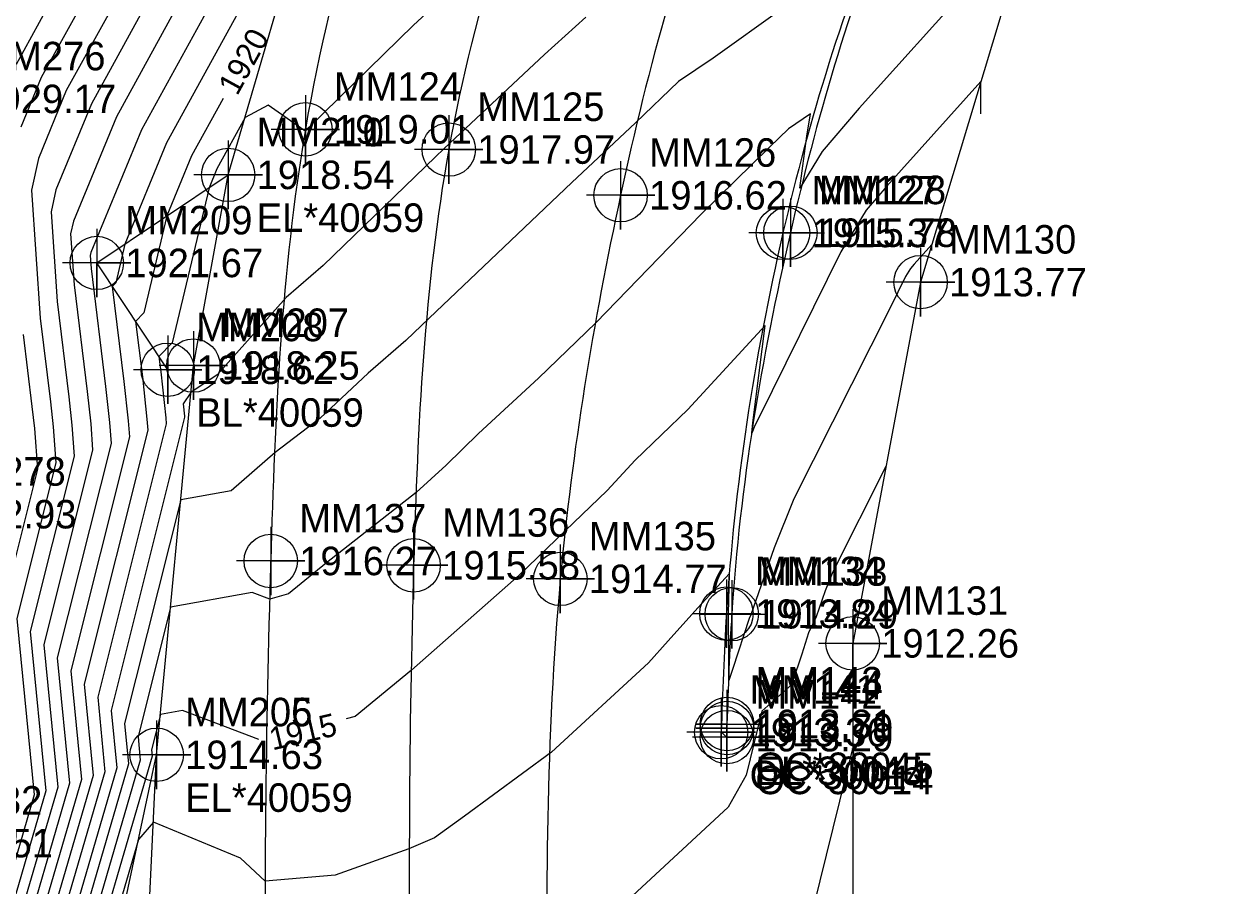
# Model space of a CAD drawing. Extents: x 1004378 to 1005103, y 553854 to 554288.
# Drawn here: x 1004979.8 to 1005086, y 554119.4 to 554194.9 of the extents above; entities that cross this region are included whole.
import ezdxf

# ---------------------------------------------------------------- set-up
doc = ezdxf.new("R2010")
doc.units = 0
for name, color, linetype in [('DTM Contours Major', 7, 'Continuous'), ('DTM Contours Major Text', 7, 'Continuous'), ('DTM Contours Minor', 7, 'Continuous'), ('Exist DTM Breakline', 7, 'Continuous'), ('Exist DTM Breakline Cogo Comment', 7, 'Continuous'), ('Exist DTM Breakline Cogo Elevation', 7, 'Continuous'), ('Exist DTM Breakline Cogo Number', 7, 'Continuous'), ('Exist DTM Breakline Cogo Point CELL', 7, 'Continuous'), ('Exist DTM Crownline', 7, 'Continuous'), ('Exist DTM Crownline Cogo Elevation', 7, 'Continuous'), ('Exist DTM Crownline Cogo Number', 7, 'Continuous'), ('Exist DTM Crownline Cogo Point CELL', 7, 'Continuous'), ('Exist Roads Curbs', 7, 'Continuous'), ('Exist Roads Curbs Cogo Comment', 7, 'Continuous'), ('Exist Roads Curbs Cogo Elevation', 7, 'Continuous'), ('Exist Roads Curbs Cogo Number', 7, 'Continuous'), ('Exist Roads Curbs Cogo Point CELL', 7, 'Continuous'), ('Exist Roads EOP', 7, 'Continuous'), ('Exist Roads EOP Cogo Comment', 7, 'Continuous'), ('Exist Roads EOP Cogo Elevation', 7, 'Continuous'), ('Exist Roads EOP Cogo Number', 7, 'Continuous'), ('Exist Roads EOP Cogo Point CELL', 7, 'Continuous')]:
    doc.layers.add(name, color=color, linetype=linetype)

msp = doc.modelspace()

# ---------------------------------------------------------------- linework, layer by layer
at = {"layer": 'DTM Contours Major'}
for points in [[(1004988.06, 554197.35), (1004983.52, 554189.09), (1004981.07, 554183.15), (1004980.47, 554180.38), (1004981.23, 554169.16), (1004982.13, 554161.83), (1004982.37, 554159.62), (1004982.6, 554156.48), (1004979.18, 554142.83), (1004980.71, 554127.37), (1004976.99, 554114.65), (1004972.24, 554102.28), (1004972.02, 554101.1)], [(1005063.7, 554187.05), (1005063.69, 554189.9), (1005055.44, 554180.71), (1005053.65, 554178.62), (1005051.42, 554174.96), (1005044.19, 554160.35), (1005043.88, 554159.74), (1005043.62, 554159.08), (1005043.7, 554159.98), (1005044.8, 554168.51), (1005038, 554161.15), (1005033.4, 554156.7), (1005030.95, 554154.05), (1005027.24, 554150.5), (1005023.22, 554146.64), (1005013.79, 554138.29), (1005008.85, 554134.25), (1005008.05, 554134.02)], [(1004997.26, 554188.39), (1004994.51, 554183.37), (1004992.34, 554178.11), (1004990.33, 554169.61), (1004989.59, 554168.86), (1004990.19, 554164.02), (1004990.59, 554160.29), (1004990.67, 554159.32), (1004985.09, 554137.07), (1004985.88, 554129.06), (1004980.68, 554111.25), (1004977.83, 554103.85), (1004975.65, 554092.33)], [(1005000.39, 554132.23), (1004993.71, 554134.75), (1004991.77, 554134.4), (1004990.99, 554131.31), (1004991.05, 554130.76), (1004984.36, 554107.86), (1004983.43, 554105.42), (1004981.8, 554096.83), (1004980.53, 554086.9), (1004982.36, 554084.87), (1004986.04, 554077.59), (1004986.97, 554072.11), (1004986.7, 554069.84), (1004986.54, 554062.8), (1004985.08, 554049.56), (1004984.33, 554046.83)]]:
    msp.add_lwpolyline(points, dxfattribs=at)
at = {"layer": 'DTM Contours Minor'}
for points in [[(1004977.31, 554222.08), (1004985.01, 554221.76), (1004987.05, 554222.46), (1004987.51, 554221.89), (1004987.45, 554221.55), (1004987.43, 554221.07), (1004987.36, 554220.82), (1004987.22, 554220.64), (1004985.6, 554198.02), (1004981.32, 554190.23), (1004979.53, 554185.89)], [(1004978.6, 554214.44), (1004982.9, 554211.38), (1004981.82, 554196.28), (1004979.12, 554191.37)], [(1005004.49, 554206.7), (1004992.31, 554184.52), (1004988.65, 554175.64), (1004987.85, 554172.24), (1004987.55, 554171.94), (1004988.57, 554163.59), (1004988.95, 554160.16), (1004989.05, 554158.75), (1004983.91, 554138.23), (1004984.84, 554128.73), (1004979.94, 554111.93)], [(1005000.71, 554204.97), (1004990.11, 554185.66), (1004985.68, 554174.91), (1004985.62, 554174.63), (1004985.7, 554173.51), (1004986.96, 554163.15), (1004987.3, 554160.02), (1004987.44, 554158.18), (1004982.73, 554139.38), (1004983.81, 554128.39), (1004979.2, 554112.61)], [(1004996.93, 554203.23), (1004987.92, 554186.8), (1004984.14, 554177.65), (1004983.9, 554176.55), (1004984.21, 554172.06), (1004985.35, 554162.71), (1004985.66, 554159.89), (1004985.83, 554157.61), (1004981.54, 554140.53), (1004982.77, 554128.05), (1004978.46, 554113.29)], [(1004993.15, 554201.49), (1004985.72, 554187.94), (1004982.61, 554180.4), (1004982.19, 554178.46), (1004982.72, 554170.61), (1004983.74, 554162.27), (1004984.01, 554159.76), (1004984.22, 554157.05), (1004980.36, 554141.68), (1004981.74, 554127.71), (1004977.73, 554113.97)], [(1005020.69, 554201.04), (1005013.96, 554194.83), (1005004.77, 554185.85), (1005004.59, 554185.68), (1005004.46, 554185.55), (1005004.34, 554185.62), (1005001.22, 554187.83), (1004999.19, 554186.75), (1004996.71, 554182.23), (1004996.03, 554180.58), (1004992.81, 554166.98), (1004991.64, 554165.79), (1004991.8, 554164.46), (1004992.24, 554160.42), (1004992.28, 554159.89), (1004986.27, 554135.92), (1004986.91, 554129.4), (1004981.41, 554110.58)], [(1005062.93, 554198.57), (1005053.02, 554187.55), (1005049.79, 554183.75), (1005047.84, 554180.55), (1005048.44, 554185.1), (1005048.77, 554187.05), (1005046.84, 554185.74), (1005045.17, 554184.14), (1005039.19, 554178.28), (1005029.95, 554168.74), (1005024.91, 554163.9), (1005019.67, 554159.04), (1005016.83, 554156.27), (1005014.19, 554153.86), (1005006.34, 554147.72), (1005003.01, 554144.99), (1005001.36, 554144.51), (1004999.81, 554145.1), (1004992.66, 554143.81), (1004989.81, 554132.46), (1004990.01, 554130.42), (1004983.63, 554108.54)], [(1005029.07, 554195.54), (1005025.44, 554192.27), (1005017.15, 554184.49), (1005016.63, 554183.99), (1005015.9, 554183.29), (1005006.03, 554173.76), (1005002.8, 554170.95), (1004996.74, 554164.18), (1004994.44, 554162.64), (1004993.77, 554161.63), (1004993.89, 554160.55), (1004993.89, 554160.46), (1004987.45, 554134.77), (1004987.95, 554129.74), (1004982.15, 554109.9)], [(1005046.28, 554196.26), (1005040.24, 554191.95), (1005037.2, 554189.88), (1005033.43, 554186.28), (1005027.84, 554181.05), (1005015.32, 554169.16), (1005013.29, 554167.2), (1005009.99, 554164.33), (1005005.79, 554160.4), (1005001.84, 554157.38), (1004997.96, 554154.02), (1004993.55, 554153.23), (1004988.63, 554133.62), (1004988.98, 554130.08), (1004982.89, 554109.22)], [(1005059.4, 554175.07), (1005059.4, 554175.6), (1005057.85, 554173.88), (1005057.52, 554173.49), (1005057.1, 554172.8), (1005055.74, 554170.07), (1005047.29, 554153.33), (1005045.59, 554149.03), (1005043.53, 554143.15), (1005043.38, 554142.84), (1005041.95, 554138.45), (1005041.61, 554137.4), (1005041.6, 554138.35), (1005041.59, 554139.54), (1005041.56, 554143.23), (1005041.66, 554146.77), (1005038.88, 554143.77), (1005036.28, 554140.86), (1005034.56, 554138.93), (1005026.07, 554131.11), (1005018.42, 554125.49), (1005015.8, 554123.59), (1005013.54, 554122.64), (1005007.08, 554120.32), (1005000.95, 554119.81), (1004998.78, 554121.81), (1004991.16, 554124.99), (1004989.85, 554123.46), (1004985.1, 554107.18)], [(1004979.74, 554167.71), (1004980.51, 554161.4), (1004980.72, 554159.49), (1004980.99, 554155.91), (1004978, 554143.99)], [(1005055.37, 554156.16), (1005050.71, 554146.92), (1005050.05, 554145.25), (1005049.25, 554142.97), (1005048.6, 554141.58), (1005047.99, 554139.71), (1005047.19, 554137.27), (1005047.12, 554137.05), (1005044.51, 554134.72), (1005043.12, 554129.11), (1005041.54, 554126.29), (1005027.19, 554113)], [(1005052.71, 554130.49), (1005052.45, 554131.42), (1005048.99, 554117.48)]]:
    msp.add_lwpolyline(points, dxfattribs=at)
at = {"layer": 'Exist DTM Breakline'}
for points in [[(1005086.04, 554233.62), (1005066.81, 554200.26), (1005058.41, 554172.31), (1005052.46, 554140.65), (1005052.44, 554096.34), (1005050.24, 554053.66), (1005047.48, 554010.1), (1005047.57, 553964.54), (1005045.23, 553915.52), (1005033.75, 553871.73)], [(1004987.71, 553883.19), (1004993.76, 553908.86), (1004995.96, 553952.19), (1004996.06, 553992.45), (1004993.93, 554035.88), (1004994.31, 554070.39), (1004993.03, 554080.74), (1004990.27, 554106.2), (1004991.44, 554130.88), (1004994.66, 554165), (1004997.71, 554181.71), (1005005.11, 554206.99)], [(1004992.41, 554164.63), (1004986.19, 554173.99), (1004997.71, 554181.71)], [(1004991.32, 554080.35), (1004986.14, 554087.98), (1004986.18, 554106.19), (1004991.44, 554130.88)]]:
    msp.add_lwpolyline(points, dxfattribs=at)
msp.add_spline([(1005062.56, 554249.27), (1005041.97, 554212.82), (1005032.11, 554179.92), (1005026.83, 554146.3), (1005025.78, 554104.32), (1005027.5, 554055.67)], degree=3, dxfattribs=at)
at = {"layer": 'Exist DTM Breakline Cogo Point CELL'}
for points in [[(1004997.71, 554184.71), (1004997.71, 554178.71), (1004997.71, 554181.71), (1005000.71, 554181.71), (1004994.71, 554181.71)], [(1004997.71, 554184.71), (1004997.71, 554178.71), (1004997.71, 554181.71), (1005000.71, 554181.71), (1004994.71, 554181.71)], [(1005032.11, 554182.92), (1005032.11, 554176.92), (1005032.11, 554179.92), (1005035.11, 554179.92), (1005029.11, 554179.92)], [(1004986.19, 554176.99), (1004986.19, 554170.99), (1004986.19, 554173.99), (1004989.19, 554173.99), (1004983.19, 554173.99)], [(1005058.41, 554175.31), (1005058.41, 554169.31), (1005058.41, 554172.31), (1005061.41, 554172.31), (1005055.41, 554172.31)], [(1004994.66, 554168), (1004994.66, 554162), (1004994.66, 554165), (1004997.66, 554165), (1004991.66, 554165)], [(1004992.41, 554167.63), (1004992.41, 554161.63), (1004992.41, 554164.63), (1004995.41, 554164.63), (1004989.41, 554164.63)], [(1005026.83, 554149.3), (1005026.83, 554143.3), (1005026.83, 554146.3), (1005029.83, 554146.3), (1005023.83, 554146.3)], [(1005052.46, 554143.65), (1005052.46, 554137.65), (1005052.46, 554140.65), (1005055.46, 554140.65), (1005049.46, 554140.65)], [(1004991.44, 554133.88), (1004991.44, 554127.88), (1004991.44, 554130.88), (1004994.44, 554130.88), (1004988.44, 554130.88)], [(1004991.44, 554133.88), (1004991.44, 554127.88), (1004991.44, 554130.88), (1004994.44, 554130.88), (1004988.44, 554130.88)]]:
    msp.add_lwpolyline(points, dxfattribs=at)
for centre in [(1004997.71, 554181.71), (1004997.71, 554181.71), (1005032.11, 554179.92), (1004986.19, 554173.99), (1005058.41, 554172.31), (1004992.41, 554164.63), (1004994.66, 554165), (1005026.83, 554146.3), (1005052.46, 554140.65), (1004991.44, 554130.88), (1004991.44, 554130.88)]:
    msp.add_circle(centre, 2.34, dxfattribs=at)
at = {"layer": 'Exist DTM Crownline'}
msp.add_spline([(1005050.59, 554258.04), (1005028.48, 554219.95), (1005017.05, 554183.93), (1005013.97, 554147.49), (1005013.77, 554103.75), (1005015.77, 554055.21)], degree=3, dxfattribs=at)
at = {"layer": 'Exist DTM Crownline Cogo Point CELL'}
for points in [[(1005017.05, 554186.93), (1005017.05, 554180.93), (1005017.05, 554183.93), (1005020.05, 554183.93), (1005014.05, 554183.93)], [(1005013.97, 554150.49), (1005013.97, 554144.49), (1005013.97, 554147.49), (1005016.97, 554147.49), (1005010.97, 554147.49)]]:
    msp.add_lwpolyline(points, dxfattribs=at)
for centre in [(1005017.05, 554183.93), (1005013.97, 554147.49)]:
    msp.add_circle(centre, 2.34, dxfattribs=at)
at = {"layer": 'Exist Roads Curbs'}
msp.add_line((1005041.44, 554133.58), (1005041.44, 554133.23), dxfattribs=at)
msp.add_spline([(1005075.03, 554240.32), (1005055.96, 554205.56), (1005047, 554176.64), (1005041.86, 554143.2), (1005041.44, 554133.58)], degree=3, dxfattribs=at)
at = {"layer": 'Exist Roads Curbs Cogo Point CELL'}
for points in [[(1005047, 554179.64), (1005047, 554173.64), (1005047, 554176.64), (1005044.27, 554176.64), (1005050, 554176.64)], [(1005041.86, 554146.2), (1005041.86, 554140.2), (1005041.86, 554143.2), (1005039.13, 554143.2), (1005044.86, 554143.2)], [(1005041.44, 554136.58), (1005041.44, 554130.58), (1005041.44, 554133.58), (1005038.71, 554133.58), (1005044.44, 554133.58)], [(1005041.44, 554136.23), (1005041.44, 554130.23), (1005041.44, 554133.23), (1005038.71, 554133.23), (1005044.44, 554133.23)]]:
    msp.add_lwpolyline(points, dxfattribs=at)
for centre in [(1005047, 554176.64), (1005041.86, 554143.2), (1005041.44, 554133.58), (1005041.44, 554133.23)]:
    msp.add_circle(centre, 2.34, dxfattribs=at)
at = {"layer": 'Exist Roads EOP'}
msp.add_line((1005040.93, 554132.86), (1005041.43, 554132.43), dxfattribs=at)
for points in [[(1005026.38, 554243.67), (1005017.05, 554225.79), (1005004.48, 554185.7), (1005001.44, 554147.87), (1005001.03, 554103.61), (1005002.79, 554054.52)], [(1005074.49, 554240.58), (1005055.68, 554205.88), (1005046.35, 554176.62), (1005041.39, 554143.25), (1005040.93, 554132.86)]]:
    msp.add_spline(points, degree=3, dxfattribs=at)
at = {"layer": 'Exist Roads EOP Cogo Point CELL'}
for points in [[(1005004.48, 554188.7), (1005004.48, 554182.7), (1005004.48, 554185.7), (1005007.48, 554185.7), (1005001.48, 554185.7)], [(1005046.35, 554179.62), (1005046.35, 554173.62), (1005046.35, 554176.62), (1005049.35, 554176.62), (1005043.35, 554176.62)], [(1005001.44, 554150.87), (1005001.44, 554144.87), (1005001.44, 554147.87), (1005004.44, 554147.87), (1004998.44, 554147.87)], [(1005041.39, 554146.25), (1005041.39, 554140.25), (1005041.39, 554143.25), (1005044.39, 554143.25), (1005038.39, 554143.25)], [(1005040.93, 554135.86), (1005040.93, 554129.86), (1005040.93, 554132.86), (1005043.93, 554132.86), (1005037.93, 554132.86)], [(1005041.43, 554135.43), (1005041.43, 554129.43), (1005041.43, 554132.43), (1005044.43, 554132.43), (1005038.43, 554132.43)]]:
    msp.add_lwpolyline(points, dxfattribs=at)
for centre in [(1005004.48, 554185.7), (1005046.35, 554176.62), (1005001.44, 554147.87), (1005041.39, 554143.25), (1005040.93, 554132.86), (1005041.43, 554132.43)]:
    msp.add_circle(centre, 2.34, dxfattribs=at)

# ---------------------------------------------------------------- texts
at = {"layer": 'DTM Contours Major Text'}
for s, rotation, p in [('1920', 61.2418, (1004998.5, 554188.57)), ('1915', 13.1372, (1005001.59, 554131.26))]:
    msp.add_text(s, height=2, rotation=rotation, dxfattribs=at).set_placement(p)
at = {"layer": 'Exist DTM Breakline Cogo Comment'}
for s, p in [('EL*40059', (1005000.21, 554176.71)), ('BL*40059', (1004994.91, 554159.63)), ('EL*40059', (1004993.94, 554125.88))]:
    msp.add_text(s, height=2.5, dxfattribs=at).set_placement(p)
at = {"layer": 'Exist DTM Breakline Cogo Elevation'}
for s, p in [('1929.17', (1004975.81, 554187.12)), ('1918.54', (1005000.21, 554180.46)), ('1918.54', (1005000.21, 554180.46)), ('1916.62', (1005034.61, 554178.67)), ('1921.67', (1004988.69, 554172.74)), ('1913.77', (1005060.91, 554171.06)), ('1918.62', (1004994.91, 554163.38)), ('1918.25', (1004997.16, 554163.75)), ('1932.93', (1004972.32, 554150.72)), ('1914.77', (1005029.33, 554145.05)), ('1912.26', (1005054.96, 554139.4)), ('1914.63', (1004993.94, 554129.63)), ('1914.63', (1004993.94, 554129.63)), ('1937.51', (1004970.27, 554121.89))]:
    msp.add_text(s, height=2.5, dxfattribs=at).set_placement(p)
at = {"layer": 'Exist DTM Breakline Cogo Number'}
for s, p in [('MM276', (1004975.81, 554190.87)), ('MM210', (1005000.21, 554184.21)), ('MM211', (1005000.21, 554184.21)), ('MM126', (1005034.61, 554182.42)), ('MM209', (1004988.69, 554176.49)), ('MM130', (1005060.91, 554174.81)), ('MM207', (1004997.16, 554167.5)), ('MM208', (1004994.91, 554167.13)), ('MM278', (1004972.32, 554154.47)), ('MM135', (1005029.33, 554148.8)), ('MM131', (1005054.96, 554143.15)), ('MM205', (1004993.94, 554133.38)), ('MM206', (1004993.94, 554133.38)), ('MM332', (1004970.27, 554125.64))]:
    msp.add_text(s, height=2.5, dxfattribs=at).set_placement(p)
at = {"layer": 'Exist DTM Crownline Cogo Elevation'}
for s, p in [('1917.97', (1005019.55, 554182.68)), ('1915.58', (1005016.47, 554146.24))]:
    msp.add_text(s, height=2.5, dxfattribs=at).set_placement(p)
at = {"layer": 'Exist DTM Crownline Cogo Number'}
for s, p in [('MM125', (1005019.55, 554186.43)), ('MM136', (1005016.47, 554149.99))]:
    msp.add_text(s, height=2.5, dxfattribs=at).set_placement(p)
at = {"layer": 'Exist Roads Curbs Cogo Comment'}
for s, p in [('OC*30045', (1005043.94, 554128.58)), ('EL*30045', (1005043.94, 554128.23))]:
    msp.add_text(s, height=2.5, dxfattribs=at).set_placement(p)
at = {"layer": 'Exist Roads Curbs Cogo Elevation'}
for s, p in [('1915.78', (1005049.5, 554175.39)), ('1914.29', (1005044.36, 554141.95)), ('1913.81', (1005043.94, 554132.33)), ('1913.79', (1005043.94, 554131.98))]:
    msp.add_text(s, height=2.5, dxfattribs=at).set_placement(p)
at = {"layer": 'Exist Roads Curbs Cogo Number'}
for s, p in [('MM128', (1005049.5, 554179.14)), ('MM133', (1005044.36, 554145.7)), ('MM143', (1005043.94, 554136.08)), ('MM144', (1005043.94, 554135.73))]:
    msp.add_text(s, height=2.5, dxfattribs=at).set_placement(p)
at = {"layer": 'Exist Roads EOP Cogo Comment'}
for p in [(1005043.43, 554127.86), (1005043.93, 554127.43)]:
    msp.add_text('OC*30014', height=2.5, dxfattribs=at).set_placement(p)
at = {"layer": 'Exist Roads EOP Cogo Elevation'}
for s, p in [('1919.01', (1005006.98, 554184.45)), ('1915.37', (1005048.85, 554175.37)), ('1916.27', (1005003.94, 554146.62)), ('1913.84', (1005043.89, 554142)), ('1913.36', (1005043.43, 554131.61)), ('1913.29', (1005043.93, 554131.18))]:
    msp.add_text(s, height=2.5, dxfattribs=at).set_placement(p)
at = {"layer": 'Exist Roads EOP Cogo Number'}
for s, p in [('MM124', (1005006.98, 554188.2)), ('MM127', (1005048.85, 554179.12)), ('MM137', (1005003.94, 554150.37)), ('MM134', (1005043.89, 554145.75)), ('MM141', (1005043.43, 554135.36)), ('MM142', (1005043.93, 554134.93))]:
    msp.add_text(s, height=2.5, dxfattribs=at).set_placement(p)

doc.saveas('drawing.dxf')
